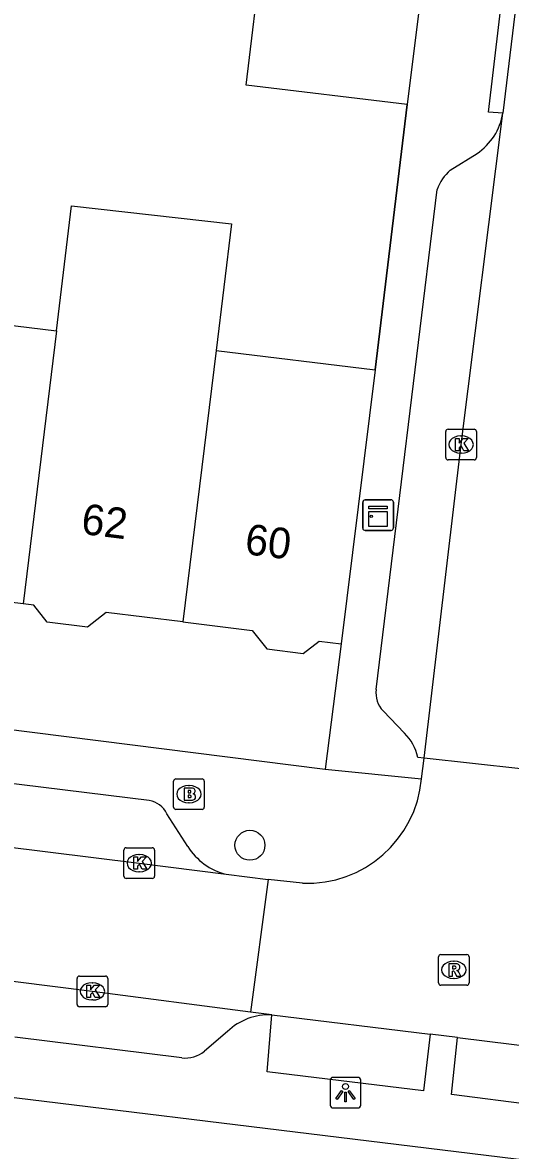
# Model space of a CAD drawing. Extents: x 158087 to 159494, y 382905 to 383981.
# Drawn here: x 158358.88 to 158374.81, y 383260.09 to 383296.93 of the extents above; entities that cross this region are included whole.
import ezdxf

# ---------------------------------------------------------------- set-up
doc = ezdxf.new("R2010")
doc.units = 0
for name, color, linetype in [('IMGEO_Boom', 7, 'Continuous'), ('IMGEO_Brandkraan', 7, 'Continuous'), ('IMGEO_Kast', 7, 'Continuous'), ('IMGEO_Kolk', 7, 'Continuous'), ('IMGEO_Lichtpunt', 7, 'Continuous'), ('IMGEO_Muur', 7, 'Continuous'), ('IMGEO_Pand', 7, 'Continuous'), ('IMGEO_Pand_nummerreeks', 7, 'Continuous'), ('IMGEO_Rijbaan_lokaal_open', 7, 'Continuous'), ('IMGEO_Rioolput', 7, 'Continuous'), ('IMGEO_Voetpad_open', 7, 'Continuous')]:
    doc.layers.add(name, color=color, linetype=linetype)

msp = doc.modelspace()

# ---------------------------------------------------------------- linework, layer by layer
at = {"layer": 'IMGEO_Boom'}
msp.add_circle((158366.305, 383270.055), 0.489, dxfattribs=at)
at = {"layer": 'IMGEO_Brandkraan'}
for p, q in [((158363.812, 383271.3), (158363.812, 383272.152)), ((158363.887, 383272.226), (158364.739, 383272.226)), ((158364.3, 383272.006), (158364.325, 383272.006)), ((158364.813, 383272.152), (158364.813, 383271.3)), ((158364.323, 383271.446), (158364.298, 383271.446)), ((158364.739, 383271.226), (158363.887, 383271.226))]:
    msp.add_line(p, q, dxfattribs=at)
for points in [[(158363.812, 383271.3), (158363.812, 383272.152)], [(158363.887, 383272.226), (158364.739, 383272.226)], [(158364.813, 383272.152), (158364.813, 383271.3)], [(158364.16, 383271.926), (158364.16, 383271.526), (158364.373, 383271.526)], [(158364.391, 383271.926), (158364.16, 383271.926)], [(158364.339, 383271.845), (158364.285, 383271.845), (158364.285, 383271.769)], [(158364.285, 383271.769), (158364.338, 383271.769)], [(158364.347, 383271.693), (158364.285, 383271.693), (158364.285, 383271.612)], [(158364.285, 383271.612), (158364.347, 383271.612)], [(158364.739, 383271.226), (158363.887, 383271.226)]]:
    msp.add_lwpolyline(points, dxfattribs=at)
for centre, radius, start, end in [((158363.889, 383272.15), 0.0765, 91.552, 178.448), ((158363.889, 383272.15), 0.0765, 91.552, 178.448), ((158364.737, 383272.15), 0.0765, 1.552, 88.448), ((158364.737, 383272.15), 0.0765, 1.552, 88.448), ((158364.34, 383271.807), 0.0379, 267.8285, 90.9355), ((158364.348, 383271.652), 0.0404, 269.8759, 90.5077), ((158364.395, 383271.781), 0.145, 59.4692, 91.5367), ((158364.42, 383271.828), 0.0922, 285.5137, 58.1501), ((158364.425, 383271.636), 0.105, 301.3115, 78.989), ((158363.889, 383271.302), 0.0765, 181.552, 268.448), ((158363.889, 383271.302), 0.0765, 181.552, 268.448), ((158364.379, 383271.777), 0.251, 268.6676, 293.5347), ((158364.737, 383271.302), 0.0765, 271.552, 358.448), ((158364.737, 383271.302), 0.0765, 271.552, 358.448)]:
    msp.add_arc(centre, radius, start, end, dxfattribs=at)
for centre, major_axis, ratio, start_param, end_param in [((158364.299, 383271.726), (-0.387, 0.002), 0.722429, 4.712389, 7.853982), ((158364.324, 383271.726), (-0.39, 0.002), 0.717154, 1.570796, 4.712389)]:
    msp.add_ellipse(centre, major_axis=major_axis, ratio=ratio, start_param=start_param, end_param=end_param, dxfattribs=at)
at = {"layer": 'IMGEO_Kast'}
for p, q in [((158369.989, 383280.415), (158369.989, 383281.256)), ((158369.989, 383281.256), (158369.989, 383280.415)), ((158370.064, 383281.34), (158370.905, 383281.34)), ((158370.905, 383281.34), (158370.064, 383281.34)), ((158370.989, 383281.265), (158370.989, 383280.424)), ((158370.989, 383280.424), (158370.989, 383281.265)), ((158370.914, 383280.34), (158370.073, 383280.34)), ((158370.073, 383280.34), (158370.914, 383280.34))]:
    msp.add_line(p, q, dxfattribs=at)
for points in [[(158370.184, 383281.13), (158370.784, 383281.13), (158370.784, 383281.045), (158370.184, 383281.045), (158370.184, 383281.13)], [(158370.184, 383280.955), (158370.784, 383280.955), (158370.784, 383280.466), (158370.184, 383280.466), (158370.184, 383280.955)]]:
    msp.add_lwpolyline(points, dxfattribs=at)
msp.add_circle((158370.268, 383280.804), 0.0377, dxfattribs=at)
for centre, start, end in [((158370.067, 383281.262), 92.4484, 184.2845), ((158370.067, 383281.262), 92.4484, 184.2845), ((158370.911, 383281.262), 2.4484, 94.2845), ((158370.911, 383281.262), 2.4484, 94.2845), ((158370.067, 383280.418), 182.4484, 274.2845), ((158370.067, 383280.418), 182.4484, 274.2845), ((158370.911, 383280.418), 272.4484, 4.2845), ((158370.911, 383280.418), 272.4484, 4.2845)]:
    msp.add_arc(centre, 0.0779, start, end, dxfattribs=at)
at = {"layer": 'IMGEO_Kolk'}
for p, q in [((158372.699, 383282.72), (158372.699, 383283.572)), ((158372.774, 383283.646), (158373.626, 383283.646)), ((158373.7, 383283.572), (158373.7, 383282.72)), ((158373.187, 383283.426), (158373.212, 383283.426)), ((158373.21, 383282.866), (158373.185, 383282.866)), ((158373.626, 383282.646), (158372.774, 383282.646)), ((158362.189, 383269.047), (158362.189, 383269.899)), ((158362.264, 383269.973), (158363.116, 383269.973)), ((158363.19, 383269.899), (158363.19, 383269.047)), ((158362.677, 383269.753), (158362.702, 383269.753)), ((158362.7, 383269.193), (158362.675, 383269.193)), ((158363.116, 383268.973), (158362.264, 383268.973)), ((158360.733, 383265.782), (158361.585, 383265.782)), ((158360.658, 383264.856), (158360.658, 383265.708)), ((158361.146, 383265.562), (158361.171, 383265.562)), ((158361.659, 383265.708), (158361.659, 383264.856)), ((158361.585, 383264.782), (158360.733, 383264.782)), ((158361.169, 383265.002), (158361.144, 383265.002))]:
    msp.add_line(p, q, dxfattribs=at)
for points in [[(158372.699, 383282.72), (158372.699, 383283.572)], [(158372.774, 383283.646), (158373.626, 383283.646)], [(158373.7, 383283.572), (158373.7, 383282.72)], [(158373.02, 383283.346), (158373.143, 383283.346), (158373.143, 383283.195), (158373.273, 383283.346), (158373.437, 383283.346), (158373.291, 383283.195), (158373.444, 383282.946), (158373.292, 383282.946), (158373.207, 383283.11), (158373.143, 383283.043), (158373.143, 383282.946), (158373.02, 383282.946), (158373.02, 383283.346)], [(158373.626, 383282.646), (158372.774, 383282.646)], [(158362.189, 383269.047), (158362.189, 383269.899)], [(158362.264, 383269.973), (158363.116, 383269.973)], [(158363.19, 383269.899), (158363.19, 383269.047)], [(158362.51, 383269.673), (158362.633, 383269.673), (158362.633, 383269.522), (158362.763, 383269.673), (158362.927, 383269.673), (158362.781, 383269.522), (158362.934, 383269.273), (158362.782, 383269.273), (158362.697, 383269.437), (158362.633, 383269.37), (158362.633, 383269.273), (158362.51, 383269.273), (158362.51, 383269.673)], [(158363.116, 383268.973), (158362.264, 383268.973)], [(158360.733, 383265.782), (158361.585, 383265.782)], [(158360.658, 383264.856), (158360.658, 383265.708)], [(158360.979, 383265.482), (158361.102, 383265.482), (158361.102, 383265.331), (158361.232, 383265.482), (158361.396, 383265.482), (158361.25, 383265.331), (158361.403, 383265.082), (158361.251, 383265.082), (158361.166, 383265.246), (158361.102, 383265.179), (158361.102, 383265.082), (158360.979, 383265.082), (158360.979, 383265.482)], [(158361.659, 383265.708), (158361.659, 383264.856)], [(158361.585, 383264.782), (158360.733, 383264.782)]]:
    msp.add_lwpolyline(points, dxfattribs=at)
for centre, start, end in [((158372.776, 383283.57), 91.552, 178.448), ((158372.776, 383283.57), 91.552, 178.448), ((158373.624, 383283.57), 1.552, 88.448), ((158373.624, 383283.57), 1.552, 88.448), ((158372.776, 383282.722), 181.552, 268.448), ((158372.776, 383282.722), 181.552, 268.448), ((158373.624, 383282.722), 271.552, 358.448), ((158373.624, 383282.722), 271.552, 358.448), ((158362.266, 383269.897), 91.552, 178.448), ((158362.266, 383269.897), 91.552, 178.448), ((158363.114, 383269.897), 1.552, 88.448), ((158363.114, 383269.897), 1.552, 88.448), ((158362.266, 383269.049), 181.552, 268.448), ((158362.266, 383269.049), 181.552, 268.448), ((158363.114, 383269.049), 271.552, 358.448), ((158363.114, 383269.049), 271.552, 358.448), ((158360.735, 383265.706), 91.552, 178.448), ((158360.735, 383265.706), 91.552, 178.448), ((158361.583, 383265.706), 1.552, 88.448), ((158361.583, 383265.706), 1.552, 88.448), ((158360.735, 383264.858), 181.552, 268.448), ((158360.735, 383264.858), 181.552, 268.448), ((158361.583, 383264.858), 271.552, 358.448), ((158361.583, 383264.858), 271.552, 358.448)]:
    msp.add_arc(centre, 0.0765, start, end, dxfattribs=at)
for centre, major_axis, ratio, start_param, end_param in [((158373.186, 383283.146), (-0.387, 0.002), 0.722429, 4.712389, 7.853982), ((158373.211, 383283.146), (-0.39, 0.002), 0.717154, 1.570796, 4.712389), ((158362.676, 383269.473), (-0.387, 0.002), 0.722429, 4.712389, 7.853982), ((158362.701, 383269.473), (-0.39, 0.002), 0.717154, 1.570796, 4.712389), ((158361.145, 383265.282), (-0.387, 0.002), 0.722429, 4.712389, 7.853982), ((158361.17, 383265.282), (-0.39, 0.002), 0.717154, 1.570796, 4.712389)]:
    msp.add_ellipse(centre, major_axis=major_axis, ratio=ratio, start_param=start_param, end_param=end_param, dxfattribs=at)
at = {"layer": 'IMGEO_Lichtpunt'}
for p, q in [((158369.828, 383262.473), (158369.02, 383262.473)), ((158369.828, 383262.473), (158369.02, 383262.473)), ((158368.926, 383262.378), (158368.926, 383261.571)), ((158368.926, 383262.378), (158368.926, 383261.571)), ((158369.922, 383261.571), (158369.922, 383262.378)), ((158369.922, 383261.571), (158369.922, 383262.378)), ((158369.02, 383261.477), (158369.828, 383261.477)), ((158369.02, 383261.477), (158369.828, 383261.477))]:
    msp.add_line(p, q, dxfattribs=at)
for points in [[(158369.3, 383262.042), (158369.339, 383262.014), (158369.151, 383261.752), (158369.113, 383261.779), (158369.3, 383262.042)], [(158369.402, 383261.994), (158369.449, 383261.994), (158369.449, 383261.672), (158369.402, 383261.672), (158369.402, 383261.994)], [(158369.512, 383262.014), (158369.55, 383262.041), (158369.737, 383261.779), (158369.698, 383261.751), (158369.512, 383262.014)]]:
    msp.add_lwpolyline(points, dxfattribs=at)
msp.add_circle((158369.425, 383262.176), 0.0994, dxfattribs=at)
for centre, start, end in [((158369.02, 383262.378), 90, 180), ((158369.02, 383262.378), 90, 180), ((158369.828, 383262.378), 0, 90), ((158369.828, 383262.378), 0, 90), ((158369.02, 383261.571), 180, 270), ((158369.02, 383261.571), 180, 270), ((158369.828, 383261.571), 270, 0), ((158369.828, 383261.571), 270, 360)]:
    msp.add_arc(centre, 0.0946, start, end, dxfattribs=at)
at = {"layer": 'IMGEO_Muur'}
msp.add_lwpolyline([(158370.391, 383285.587), (158371.444, 383294.256)], dxfattribs=at)
at = {"layer": 'IMGEO_Pand'}
for points in [[(158371.444, 383294.256), (158366.184, 383294.89), (158366.696, 383299.14)], [(158371.966, 383298.459), (158371.444, 383294.256)], [(158359.987, 383286.861), (158360.477, 383290.946), (158365.703, 383290.356), (158365.196, 383286.223)], [(158354.528, 383287.529), (158359.987, 383286.861)], [(158359.987, 383286.861), (158358.896, 383277.942)], [(158365.196, 383286.223), (158364.109, 383277.353)], [(158365.196, 383286.223), (158370.391, 383285.587)], [(158370.391, 383285.587), (158369.28, 383276.64)], [(158358.896, 383277.942), (158353.435, 383278.611)], [(158364.109, 383277.353), (158361.605, 383277.66), (158360.999, 383277.186), (158359.683, 383277.347), (158359.251, 383277.899), (158358.896, 383277.942)], [(158364.109, 383277.353), (158366.38, 383277.075), (158366.855, 383276.468), (158368.045, 383276.322), (158368.564, 383276.727), (158369.28, 383276.64)]]:
    msp.add_lwpolyline(points, dxfattribs=at)
at = {"layer": 'IMGEO_Rijbaan_lokaal_open'}
for points in [[(158375.105, 383298.488), (158374.568, 383293.97)], [(158371.99, 383272.904), (158373.202, 383283.146), (158374.568, 383293.97)], [(158316.441, 383275.218), (158319.512, 383274.807), (158336.396, 383272.726), (158346.217, 383271.509), (158350.74, 383270.948), (158362.686, 383269.472), (158365.523, 383269.112)], [(158371.91, 383272.225), (158371.99, 383272.904)], [(158375.153, 383272.548), (158371.99, 383272.904)], [(158365.523, 383269.112), (158366.905, 383268.943)], [(158366.905, 383268.943), (158366.328, 383264.605)], [(158368.024, 383268.815), (158366.905, 383268.943)], [(158366.328, 383264.605), (158361.155, 383265.283), (158356.136, 383265.91)], [(158367.019, 383264.514), (158366.328, 383264.605)], [(158367.019, 383264.514), (158372.191, 383263.882)], [(158373.079, 383263.774), (158372.191, 383263.882)], [(158373.079, 383263.774), (158378.545, 383263.106)]]:
    msp.add_lwpolyline(points, dxfattribs=at)
msp.add_arc((158368.173, 383272.564), 3.752, 267.7241, 354.8104, dxfattribs=at)
at = {"layer": 'IMGEO_Rioolput'}
for p, q in [((158372.539, 383266.485), (158373.391, 383266.485)), ((158372.464, 383265.559), (158372.464, 383266.411)), ((158372.952, 383266.265), (158372.977, 383266.265)), ((158373.465, 383266.411), (158373.465, 383265.559)), ((158373.391, 383265.485), (158372.539, 383265.485)), ((158372.975, 383265.705), (158372.95, 383265.705))]:
    msp.add_line(p, q, dxfattribs=at)
for points in [[(158372.539, 383266.485), (158373.391, 383266.485)], [(158372.464, 383265.559), (158372.464, 383266.411)], [(158373.053, 383266.183), (158372.801, 383266.185), (158372.801, 383265.785)], [(158373.465, 383266.411), (158373.465, 383265.559)], [(158372.801, 383265.785), (158372.925, 383265.785), (158372.925, 383265.947), (158372.936, 383265.947)], [(158372.979, 383266.104), (158372.925, 383266.104), (158372.925, 383266.023)], [(158372.925, 383266.023), (158372.977, 383266.023)], [(158372.983, 383265.918), (158373.054, 383265.785), (158373.194, 383265.785), (158373.129, 383265.911)], [(158373.391, 383265.485), (158372.539, 383265.485)]]:
    msp.add_lwpolyline(points, dxfattribs=at)
for centre, radius, start, end in [((158372.541, 383266.409), 0.0765, 91.552, 178.448), ((158372.541, 383266.409), 0.0765, 91.552, 178.448), ((158373.389, 383266.409), 0.0765, 1.552, 88.448), ((158373.389, 383266.409), 0.0765, 1.552, 88.448), ((158373.052, 383266.073), 0.109, 350.3612, 89.416), ((158372.935, 383265.894), 0.0533, 26.0293, 88.6989), ((158372.961, 383266.212), 0.19, 274.7715, 282.9687), ((158372.985, 383266.008), 0.0964, 77.0061, 93.1865), ((158372.999, 383266.065), 0.0378, 276.6634, 79.6772), ((158373.05, 383266.073), 0.112, 277.5842, 350.9817), ((158373.034, 383265.858), 0.108, 29.5134, 73.7905), ((158372.541, 383265.561), 0.0765, 181.552, 268.448), ((158372.541, 383265.561), 0.0765, 181.552, 268.448), ((158373.389, 383265.561), 0.0765, 271.552, 358.448), ((158373.389, 383265.561), 0.0765, 271.552, 358.448)]:
    msp.add_arc(centre, radius, start, end, dxfattribs=at)
for centre, major_axis, ratio, start_param, end_param in [((158372.951, 383265.985), (-0.387, 0.002), 0.722429, 4.712389, 7.853982), ((158372.976, 383265.985), (-0.39, 0.002), 0.717154, 1.570796, 4.712389)]:
    msp.add_ellipse(centre, major_axis=major_axis, ratio=ratio, start_param=start_param, end_param=end_param, dxfattribs=at)
at = {"layer": 'IMGEO_Voetpad_open'}
for points in [[(158374.568, 383293.97), (158374.1, 383294.004), (158374.635, 383298.539), (158375.105, 383298.488)], [(158371.444, 383294.256), (158370.391, 383285.587)], [(158372.848, 383292.106), (158373.722, 383292.655)], [(158370.427, 383275.142), (158372.424, 383291.477)], [(158315.314, 383279.287), (158346.553, 383275.453), (158358.185, 383274.026), (158358.16, 383273.883), (158368.763, 383272.542)], [(158363.015, 383271.514), (158319.388, 383276.89)], [(158369.28, 383276.64), (158368.763, 383272.542)], [(158371.353, 383273.72), (158370.653, 383274.444)], [(158371.99, 383272.904), (158371.783, 383272.927)], [(158368.763, 383272.542), (158371.91, 383272.225)], [(158364.275, 383270.012), (158363.586, 383271.084)], [(158372.191, 383263.882), (158371.975, 383262.032), (158366.866, 383262.654), (158367.019, 383264.514)], [(158365.571, 383263.973), (158364.816, 383263.328)], [(158364.081, 383263.113), (158358.622, 383263.791)], [(158378.545, 383263.106), (158378.31, 383261.219), (158372.892, 383261.916), (158373.079, 383263.774)], [(158353.332, 383262.456), (158436.049, 383252.351), (158455.212, 383250), (158496.63, 383244.919)]]:
    msp.add_lwpolyline(points, dxfattribs=at)
for centre, radius, start, end in [((158372.609, 383294.3), 1.986, 304.0659, 350.424), ((158373.711, 383291.067), 1.35, 129.7034, 162.3299), ((158371.302, 383275.04), 0.881, 173.3345, 222.5476), ((158370.213, 383272.589), 1.606, 12.1556, 44.7815), ((158362.908, 383270.778), 0.744, 24.2888, 81.747), ((158366.017, 383271.112), 2.06, 212.2763, 256.1289), ((158366.918, 383262.576), 1.94, 87.012, 133.9612), ((158364.205, 383264.054), 0.949, 262.5022, 310.108)]:
    msp.add_arc(centre, radius, start, end, dxfattribs=at)

# ---------------------------------------------------------------- texts
at = {"layer": 'IMGEO_Pand_nummerreeks'}
for s, p in [('62', (158360.762, 383280.234)), ('60', (158366.105, 383279.573))]:
    msp.add_text(s, height=1, rotation=352.9371, dxfattribs=at).set_placement(p)

doc.saveas('drawing.dxf')
